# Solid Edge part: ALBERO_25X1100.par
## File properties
Subject: ALBERO_25X1100
Author: f_grande
Template: Normal.par
Last saved by: f_grande
Revision: 2
Application: Solid Edge
Material: Acciaio
Stile della faccia: Acciaio
Stile di riempimento: ANSI32(Acciaio)
Stile virtuale: Acciaio lavorato a macchina
Coef. of Thermal Exp: 0.0
Thermal Conductivity: 32.0
Specific Heat: 481.0
Modulus of Elasticity: 199947953000.0
Poisson's Ratio: 0.29
Yield Stress: 262000766.0
Ultimate Stress: 358527364.0
Elongation: 0.0
Tipo di contenuto documento: 0
Densità: 7833,000 kg/m^3
Precisione: 0,990
Document Number: KRO102
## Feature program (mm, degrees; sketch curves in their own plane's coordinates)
sketch for "unnamed Protrusion 1" plane through (0, 0, 0) normal (0, -1, 0) x-axis (1, 0, 0)
  circle centre (0, 0) radius 12.5
extrude "unnamed Protrusion 1" add finite 1100 along -normal
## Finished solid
Body 1: solid body, 3 faces, 2 edges, 0 vertices.
  Faces by surface: plane 2, cylinder 1
  Edges by curve: circle 2
Bounding box of the edges (mm): 25.000 x 1100.000 x 25.000, from (-12.5, 0, -12.5) to (12.5, 1100, 12.5).
Cylindrical faces by radius (mm): R12.5 x1
Planar faces by outward normal: +y 1, -y 1
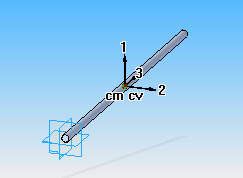
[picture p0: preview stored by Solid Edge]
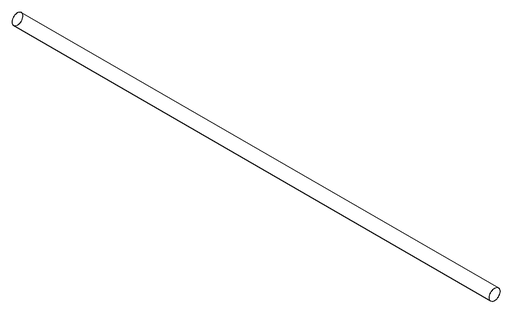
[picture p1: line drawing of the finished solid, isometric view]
